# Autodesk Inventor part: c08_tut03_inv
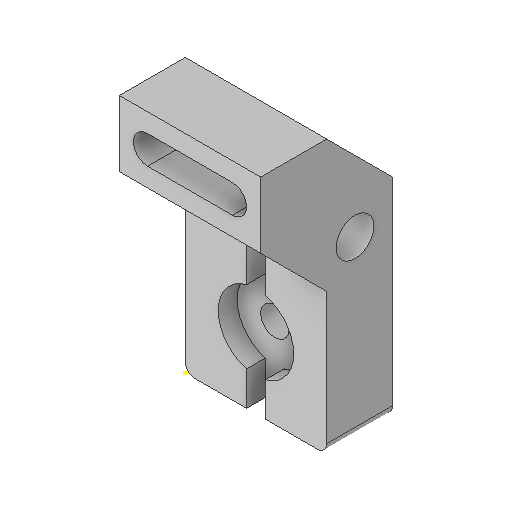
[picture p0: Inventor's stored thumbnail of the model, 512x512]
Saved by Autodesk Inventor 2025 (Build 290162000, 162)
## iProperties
Created: 2015-03
Part Number: c08_tut03_inv
Material: Generic
Document SubType Name: Modeling
Designer: Sandeep
Density: 1 g/cm^3
Appearance: Default
Author: Sandeep
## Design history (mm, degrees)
sketch "Sketch1"
  geometry: L1 (0, 0)-(0, 30); L2 (0, 30)-(-14, 44); L3 (-14, 44)-(-14, 58); L4 (-14, 58)-(0, 58); L5 (14, 44)-(14, 0); L6 (14, 0)-(0, 0); L7 (0, 58)-(14, 44)
  constraints: 14 end point, 3 parallel, 1 horizontal, 1 perpendicular, 1 vertical
  dimensions: "d0" = 14 distance between parallel lines of L5 L1; "d1" = 14 distance from line of L4.end L5; "d2" = 14 horizontal distance of L4.end L5.start; "d3" = 28 distance between parallel lines of L3 L5; "d4" = 58 distance between parallel lines of L4 L6; "d5" = 14 distance of L2.end L3.end
extrude "Extrusion1" new body sketch "Sketch1" distance "d6" = 30; taper "d7" = 0 deg
hole "Hole1" diameter "d10" = 8; stored, may be unused: countersink angle "d14" = 90 deg, drill point angle "d16" = 118 deg; dims "d8" = 21, "d9" = 8, "d11" = 6, "d12" = 4, "d13" = 2, "d15" = 8
sketch "Sketch3"
  geometry: L1 (0, 0)-(30, 0) reference; L2 (0, -30)-(30, -30) reference; L3 (30, 0)-(30, -30) reference; L4 (13, 0)-(13, -7.254); L5 (0, 3)-(30, 3) reference; L6 (17, 0)-(17, -7.254); L7 (15, -15)-(15, 7.075); L8 (13, 0)-(17, 0); L9 (-6.754, -15)-(33.848, -15); L10 (13, -22.746)-(13, -30); L11 (17, -30)-(17, -22.746); C1 r 3 at (15, -15); A1 r 8 centre (15, -15) between (13, -7.254) and (13, -22.746); A2 r 8 centre (15, -15) between (17, -22.746) and (17, -7.254)
  constraints: 14 end point, 5 point on line, 4 point on circle, 3 centre point, 2 parallel, 2 perpendicular, 1 coincident, 1 collinear, 1 horizontal, 1 vertical, 2 other
  dimensions: "d19" = 6 diameter of C1; "d21" = 15 distance from line of L2 A1.centre; "d22" = 15 distance from line of A1.centre L3; "d23" = 4 distance between parallel lines of L6 L4; "d24" = 4 distance between parallel lines of L11 L10; "d25" = 8 radius of A2; "d26" = 8 radius of A1
extrude "Extrusion2" cut sketch "Sketch3" distance "d27" = 4; taper "d28" = 0 deg
sketch "Sketch5"
  geometry: L1 (6, 7)-(24, 7); L2 (6, 4)-(24, 4); L3 (24, 10)-(6, 10); L4 (0, 14)-(30, 14) reference; L5 (30, 0)-(30, 14) reference; A1 r 3 centre (6, 7) between (6, 10) and (6, 4); A2 r 3 centre (24, 7) between (24, 4) and (24, 10); 2 further points
  constraints: 8 end point, 4 point on circle, 4 tangent, 2 centre point, 1 horizontal, 1 midpoint, 1 parallel
  dimensions: "d29" = 7 distance between parallel lines of L4 L1; "d30" = 18 distance of L1.start L1.end; "d31" = 6 distance from line of L5 L1.end; "d32" = 3 radius of A2
extrude "Extrusion3" cut sketch "Sketch5" distance "d33" = 11; taper "d34" = 0 deg
sketch "Sketch6"
  geometry: C1 r 3 at (0, 0); C2 r 3 at (0, 0) reference; 1 further point
  constraints: 1 centre point, 1 concentric
extrude "Extrusion4" cut sketch "Sketch6" distance "d35" = 35.25; taper "d36" = 0 deg
fillet "Fillet2" dims "d37" = 2
body "Solid1"
sketch "Sketch2"
  geometry: 1 further point
sketch "Sketch4"
  geometry: 1 further point
other parameters: "d20" = 16
